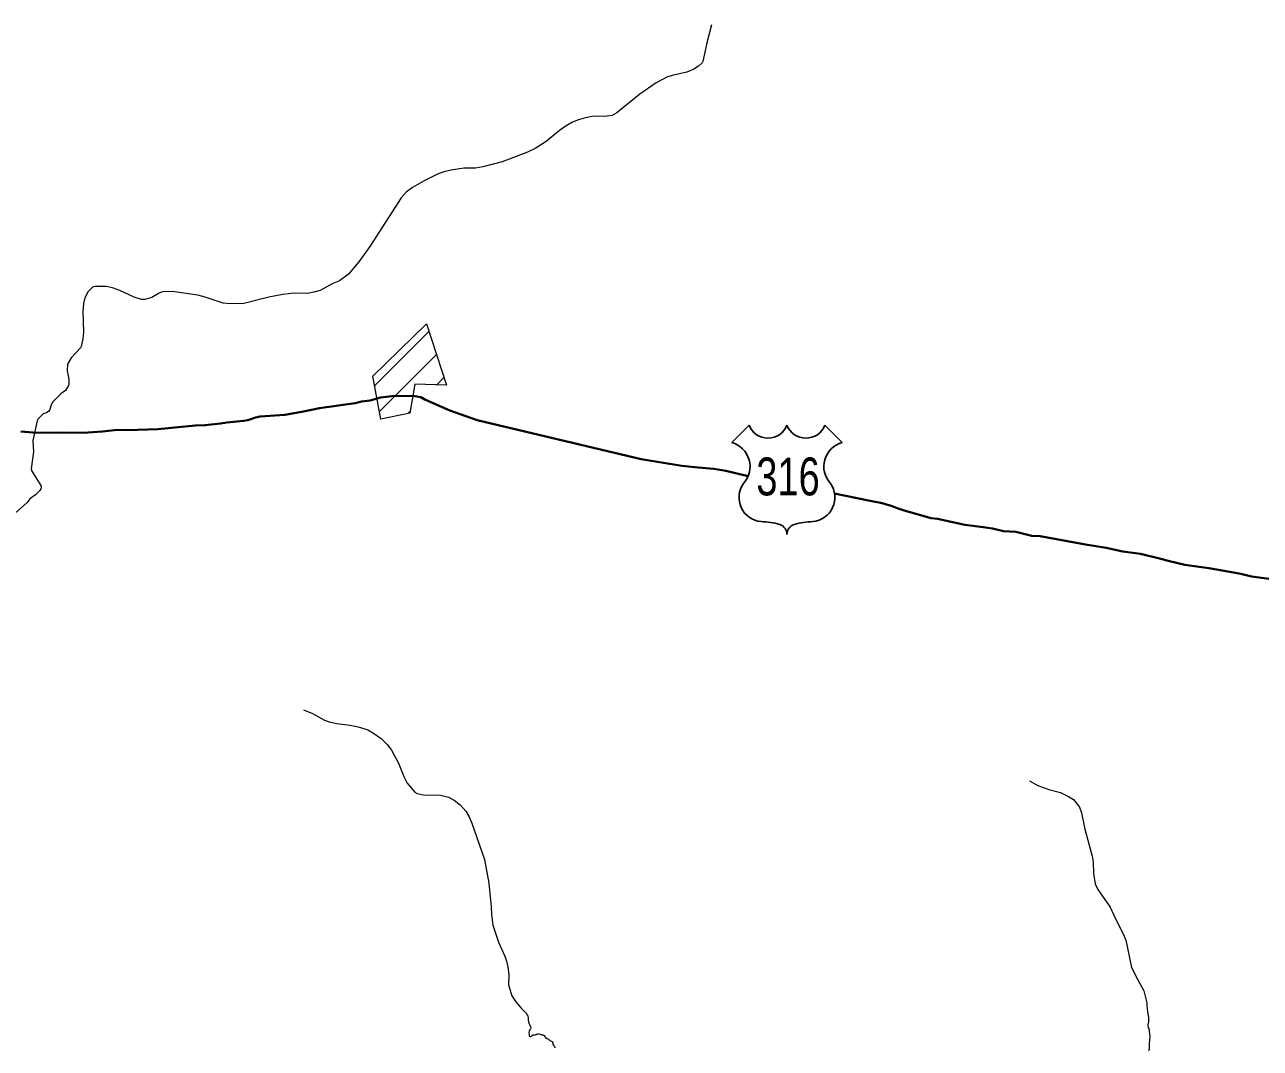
# Model space of a CAD drawing. Extents: x 553962 to 842807, y 8883888 to 9032388.
# Drawn here: x 611890 to 614173, y 8911161 to 8913052 of the extents above; entities that cross this region are included whole.
import ezdxf
from ezdxf.enums import TextEntityAlignment as Align

# ---------------------------------------------------------------- set-up
doc = ezdxf.new("R2010")
doc.units = 0
doc.header["$LTSCALE"] = 200
doc.layers.add('6', color=7, linetype='Continuous', lineweight=13)

msp = doc.modelspace()

# ---------------------------------------------------------------- linework, layer by layer
at = {"layer": '6'}
for p, q in [((612536.6, 8912385.5), (612637.1, 8912486)), ((612545.6, 8912337.9), (612650.9, 8912443.2)), ((612651.1, 8912386.8), (612664.7, 8912400.5)), ((612598.1, 8912333.9), (612602.5, 8912338.2))]:
    msp.add_line(p, q, dxfattribs=at)
at = {"layer": '6', "lineweight": 25}
for p, q in [((613196.5, 8912280.5), (613228.5, 8912312.5)), ((613368.3, 8912312.5), (613400.3, 8912280.5))]:
    msp.add_line(p, q, dxfattribs=at)
at = {"layer": '6'}
for points in [[(613159.1, 8913052.5), (613150.7, 8913018.9), (613143.3, 8912984.7), (613141.8, 8912982.2), (613135, 8912975.7), (613126.6, 8912970.5), (613113.2, 8912965.1), (613088.7, 8912959.4), (613077.6, 8912955.9), (613056.8, 8912945.1), (613026.4, 8912924.2), (612984.3, 8912889.5), (612975.3, 8912885), (612962, 8912882.7), (612949.3, 8912883.3), (612938.2, 8912882.9), (612926.3, 8912880.4), (612913.6, 8912876.7), (612902.5, 8912872.2), (612890.6, 8912865.5), (612878, 8912856.9), (612853.6, 8912836.8), (612833.4, 8912823.5), (612819.3, 8912816.9), (612772.4, 8912799.4), (612736.7, 8912790.1), (612723.2, 8912787.6), (612701.8, 8912787.2), (612678, 8912783.9), (612664.5, 8912780.4), (612652.7, 8912776.3), (612628.1, 8912764), (612606.6, 8912751.9), (612595.2, 8912743), (612585.7, 8912732.6), (612528.2, 8912642.8), (612507.4, 8912614.5), (612488.7, 8912591.9), (612472.2, 8912579.6), (612459.6, 8912574.3), (612436.4, 8912561.7), (612424.6, 8912558.2), (612412.7, 8912555.7), (612388.1, 8912556.3), (612367.4, 8912554.2), (612341.2, 8912549.2), (612295.2, 8912537.7), (612271.4, 8912536.9), (612257.2, 8912538.1), (612223.7, 8912549.1), (612210.3, 8912552.6), (612162.7, 8912559.7), (612144.9, 8912558.7), (612138.8, 8912556.3), (612125.4, 8912548.8), (612112.3, 8912544.7), (612106, 8912544.6), (612092.8, 8912549.1), (612065.9, 8912561.3), (612052.4, 8912566.6), (612041.2, 8912568.8), (612020.6, 8912568.7), (612015.4, 8912567.7), (612007.7, 8912559.9), (612001.2, 8912548)], [(612001.2, 8912548), (611998.8, 8912537.7), (611997.8, 8912523.3), (611998.9, 8912484.2), (611997.9, 8912472.3), (611995, 8912458.1), (611993.6, 8912455.4), (611976.2, 8912436.9), (611969.4, 8912425.1), (611969, 8912412.8), (611971.8, 8912397.5), (611972.1, 8912388.9), (611971.3, 8912385.8), (611966.1, 8912376.9), (611957.4, 8912370.8), (611942.7, 8912356), (611939.6, 8912350.1), (611936.9, 8912341.8), (611934.1, 8912337.6), (611931.6, 8912335.8), (611923.8, 8912332.9), (611915.6, 8912324.2), (611913.7, 8912320.5), (611910.8, 8912309.8), (611905.7, 8912284.3), (611906.7, 8912263.3), (611902.5, 8912231.9), (611903.9, 8912227.7), (611920, 8912201.1), (611920.7, 8912198.1), (611920.3, 8912194.8), (611918.3, 8912191.9), (611910.3, 8912183.8), (611900.1, 8912176.6), (611894.1, 8912169.3), (611873.3, 8912150.5)], [(612405.4, 8911786.9), (612421.9, 8911779.7), (612444.2, 8911767.9), (612452.9, 8911764.7), (612467, 8911761.3), (612491.4, 8911758.4), (612508.9, 8911754.9), (612524, 8911749.8), (612535, 8911743.9), (612548.6, 8911733.8), (612559.7, 8911722.7), (612568.1, 8911711.9), (612580.6, 8911688.2), (612590.9, 8911663.6), (612597.2, 8911651.2), (612610.8, 8911634.7), (612615.1, 8911632.4), (612626.2, 8911629.9), (612658.6, 8911628.8), (612673.5, 8911625.1), (612683.9, 8911620.1), (612694.8, 8911611.3), (612705, 8911599.6), (612711.5, 8911589.3), (612716.3, 8911577.6), (612739.5, 8911510.5), (612747.7, 8911466.3), (612752.2, 8911422.9), (612752.6, 8911408.8), (612755.4, 8911389), (612765.9, 8911357.3), (612777.4, 8911331.4), (612780.4, 8911322.6), (612782.9, 8911311.6), (612784.4, 8911297.5), (612784.2, 8911278.4), (612790.5, 8911258.6), (612797.4, 8911247.3), (612807.2, 8911235.8), (612817.1, 8911225.9)], [(613746.6, 8911655.6), (613761.8, 8911647), (613782.4, 8911639.6), (613803.8, 8911633.7), (613818.3, 8911626.8), (613827.9, 8911620.8), (613832.9, 8911615.2), (613838.7, 8911606.9), (613842.3, 8911596.7), (613848.4, 8911566.1), (613862.4, 8911516.5), (613864.1, 8911505.6), (613864.4, 8911484.4), (613867.7, 8911465.5), (613872.8, 8911454.6), (613895.5, 8911422.3), (613905.6, 8911400.5), (613920.2, 8911371.9), (613924.2, 8911361), (613935.1, 8911310.7), (613946.5, 8911288.1), (613957.4, 8911267.5), (613963, 8911245.3)], [(613963, 8911245.3), (613963.4, 8911239.5), (613963.5, 8911237), (613964, 8911233.7), (613964.6, 8911229.1), (613965.9, 8911221.6), (613966.2, 8911220), (613966.3, 8911218.8), (613966.4, 8911218.5)], [(612817.1, 8911225.9), (612817.4, 8911225), (612818, 8911223.9), (612818.6, 8911222.4), (612819.6, 8911220.8), (612820.4, 8911219.5), (612820.6, 8911218.7), (612820.6, 8911217.4), (612820.3, 8911215.9), (612820.2, 8911213.9), (612820.4, 8911213), (612821.1, 8911211.6), (612821.3, 8911210.5), (612821, 8911209.4)], [(613966, 8911218.5), (613966.2, 8911213.3), (613966.1, 8911210.4), (613965.8, 8911207), (613965.3, 8911205.2), (613964.9, 8911202.2), (613965.7, 8911199.6), (613966.6, 8911197.7), (613967.8, 8911188.8), (613968.6, 8911182.6), (613968.1, 8911177), (613967.4, 8911169.7), (613967.3, 8911166.2), (613967.7, 8911163.2), (613967.1, 8911156.4)], [(612821, 8911209.4), (612821.6, 8911208.3), (612822.4, 8911206.7), (612823.2, 8911204.4), (612824.9, 8911200.9), (612825.3, 8911199.8), (612825.2, 8911198.6), (612824.6, 8911197.1), (612823.1, 8911195.1), (612822, 8911193.1), (612821.4, 8911190.8), (612822.3, 8911187), (612822.3, 8911184.5), (612822.3, 8911183.5)], [(612822.3, 8911183.6), (612823.9, 8911183.1), (612824.8, 8911183), (612825.5, 8911183.1), (612826.4, 8911183.6), (612827.5, 8911185), (612828.1, 8911185.7), (612829, 8911186), (612830.5, 8911186), (612832.3, 8911185.9), (612834.3, 8911186.6), (612835.2, 8911187), (612837.1, 8911188), (612838.2, 8911188.2), (612839.3, 8911188), (612841.9, 8911187.6), (612843.1, 8911187.2), (612844.3, 8911186.8), (612845.2, 8911186.6)], [(612845.8, 8911186.4), (612847.8, 8911186.2), (612848.8, 8911185.9), (612850.1, 8911185.3), (612851.1, 8911183.4), (612851.8, 8911182.1), (612853.2, 8911180.4), (612854.8, 8911179.4), (612856.6, 8911178.8), (612858, 8911178), (612859.3, 8911176.8), (612860.2, 8911175.8), (612861.6, 8911175.2), (612863.6, 8911174.4), (612864.9, 8911173.1), (612865.7, 8911171.2), (612866, 8911169.8), (612866.6, 8911168.1), (612868, 8911166.1), (612868.8, 8911164.7), (612869.4, 8911162.7), (612869.5, 8911162.2)]]:
    msp.add_lwpolyline(points, dxfattribs=at)
msp.add_lwpolyline([(612533.2, 8912403.4), (612632.5, 8912500.1), (612669.3, 8912386.3), (612611.2, 8912388.1), (612601.8, 8912334.6), (612548.3, 8912323.5)], close=True, dxfattribs=at)
at = {"layer": '6', "lineweight": 40}
for points in [[(611883.1, 8912301.1), (611912.9, 8912298.6), (611956.6, 8912299.4), (611998, 8912298.2), (612034.4, 8912300.8), (612062.1, 8912304), (612080.2, 8912303.3), (612136.2, 8912305), (612205.9, 8912312.1), (612224, 8912312.5), (612252.3, 8912315.6), (612263.9, 8912317.7), (612294.8, 8912320.4), (612302.5, 8912322), (612316.8, 8912326.8), (612325.2, 8912328.8), (612370.8, 8912332), (612405.4, 8912337.7), (612435.2, 8912344), (612500.6, 8912353.4), (612512.3, 8912356.6), (612528.3, 8912358.5), (612547.5, 8912363.6), (612568.3, 8912366), (612607.2, 8912366.8), (612622, 8912364.3), (612629.4, 8912360.3), (612675.8, 8912339.5), (612726, 8912322.1), (613028.9, 8912249.9)], [(613028.9, 8912249.9), (613104.3, 8912237.7), (613134.5, 8912234.3), (613163.2, 8912232.2), (613185.3, 8912228.2), (613226.8, 8912218.5)], [(613386.4, 8912186.2), (613401.2, 8912183.6), (613452.1, 8912172.7), (613474.2, 8912168.8), (613491.2, 8912163.9), (613503.7, 8912158.5), (613514.7, 8912154.8), (613564.8, 8912141), (613576.6, 8912139.3), (613626.7, 8912128.5), (613660.6, 8912124.5), (613678.3, 8912121.5), (613698.2, 8912117), (613721.1, 8912115.6), (613750.5, 8912108.4), (613766.3, 8912107.4), (613849.7, 8912091.9), (613888.1, 8912085.9), (613919, 8912079.5), (613951.5, 8912074.8), (613991.2, 8912065.2), (614002.3, 8912061.8), (614033.2, 8912054.9), (614077.8, 8912048.2), (614095.5, 8912045.1)], [(614095.5, 8912045.1), (614137.1, 8912037.7), (614156.6, 8912033.3), (614189.2, 8912028.5), (614215.5, 8912021.7), (614263.5, 8912005.4), (614314.9, 8911983.3), (614359.3, 8911958.1), (614413.5, 8911919.6), (614418.7, 8911918.6), (614421.7, 8911917.2), (614435.2, 8911906.1)]]:
    msp.add_lwpolyline(points, dxfattribs=at)
at = {"layer": '6', "lineweight": 25}
for centre, radius, start, end in [((613263.4, 8912325.9), 37.4, 200.9593, 339.0407), ((613333.4, 8912325.9), 37.4, 200.9593, 339.0407), ((613184.1, 8912236.1), 46.1, 317.5721, 74.3689), ((613412.7, 8912236.1), 46.1, 105.6277, 222.4279), ((613254.8, 8912179.1), 44.9, 144.7373, 264.6578), ((613342, 8912179.1), 44.9, 275.3422, 35.2627), ((613250.4, 8912016.4), 118, 72.8937, 89.9006), ((613346.4, 8912016.4), 118, 90.0994, 107.1063), ((613279.5, 8912111.1), 18.9, 357.6934, 72.9296), ((613317.3, 8912111.1), 18.9, 107.0704, 182.3065)]:
    msp.add_arc(centre, radius, start, end, dxfattribs=at)

# ---------------------------------------------------------------- texts
at = {"layer": '6', "width": 0.75}
msp.add_text('316', height=70, dxfattribs=at).set_placement((613300.4, 8912182.9), align=Align.CENTER)

doc.saveas('drawing.dxf')
